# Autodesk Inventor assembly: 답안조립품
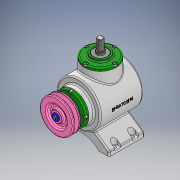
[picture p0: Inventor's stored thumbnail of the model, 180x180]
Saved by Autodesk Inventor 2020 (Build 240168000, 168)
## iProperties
Created: 2023-12
Part Number: 답안조립품
Document SubType Name: Weldment
Designer: 1강의실14
Weld Material: Welded Aluminum-6061
Author: 1강의실14
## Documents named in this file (17)
- C:\Users\1강의실14\Desktop\731203V1009\답안조립품.iam
- C:\Users\1강의실14\Desktop\731203V1009\본체.ipt
- C:\Users\1강의실14\Desktop\731203V1009\커버.ipt
- C:\Users\1강의실14\Desktop\731203V1009\베어링 6203.ipt
- C:\Users\1강의실14\Desktop\731203V1009\볼트 M4 x 10.ipt
- C:\Users\1강의실14\Desktop\731203V1009\서브 축.ipt
- 서브 축.ipt
- C:\Users\1강의실14\Desktop\731203V1009\메인 축.ipt
- 메인 축.ipt
- C:\Users\1강의실14\Desktop\731203V1009\키 5 x 5 x 14.ipt
- C:\Users\1강의실14\Desktop\731203V1009\키 4 x 4 x 14.ipt
- C:\Users\1강의실14\Desktop\731203V1009\메인 베벨기어.ipt
- C:\Users\1강의실14\Desktop\731203V1009\서브 베벨기어.ipt
- C:\Users\1강의실14\Desktop\731203V1009\오일실 17 x 32 x 8.ipt
- C:\Users\1강의실14\Desktop\731203V1009\V-벨트풀리.ipt
- C:\Users\1강의실14\Desktop\731203V1009\와셔 4 x 16.ipt
- C:\Users\1강의실14\Desktop\731203V1009\육각볼트 M4 x 8.ipt
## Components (1 placed, 1 different names)
1. V-벨트풀리:1 — 플러쉬:1
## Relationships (1: Flush 1)
- 플러쉬:1 [Flush]: V-벨트풀리:1
